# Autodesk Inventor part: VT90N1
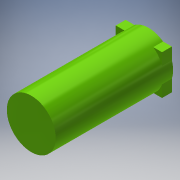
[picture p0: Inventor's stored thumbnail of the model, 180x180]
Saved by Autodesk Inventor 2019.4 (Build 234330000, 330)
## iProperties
Created: 2019-11
Part Number: VT90N1
Material: Generic
Document SubType Name: Modeling
Designer: Willist
Density: 1 g/cm^3
Appearance: VT900, VT90N1
Author: Willist
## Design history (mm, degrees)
sketch "VT900, VT90N1_73"
  geometry: L1 (-2.413, 2.077)-(2.312, 2.077); L2 (2.312, 2.077)-(2.312, -1.975); L3 (2.312, -1.975)-(-2.413, -1.975); L4 (-2.413, -1.975)-(-2.413, 2.077)
  constraints: 8 end point
extrude "Extrusion1" join sketch "VT900, VT90N1_73" distance "d0" = 1; taper "d1" = 0 deg
sketch "Sketch2"
  geometry: L1 (2.312, 2.077)-(-2.413, 2.077) reference; L2 (-2.413, -1.975)-(2.312, -1.975) reference; L3 (-2.413, 2.077)-(2.312, 2.077); L4 (2.312, 2.077)-(2.312, -1.975); L5 (2.312, -1.975)-(-2.413, -1.975); L6 (-2.413, -1.975)-(-2.413, 2.077); C1 r 2.5 at (-0.051, 0.051); 1 further point
  constraints: 8 end point, 2 parallel, 1 centre point, 1 horizontal, 1 perpendicular
  dimensions: "d2" = 5 diameter of C1
extrude "Extrusion2" join sketch "Sketch2" distance "d3" = 11; taper "d5" = 0 deg; dims "d4" = 1, "d6" = 0
body "Solid1"
